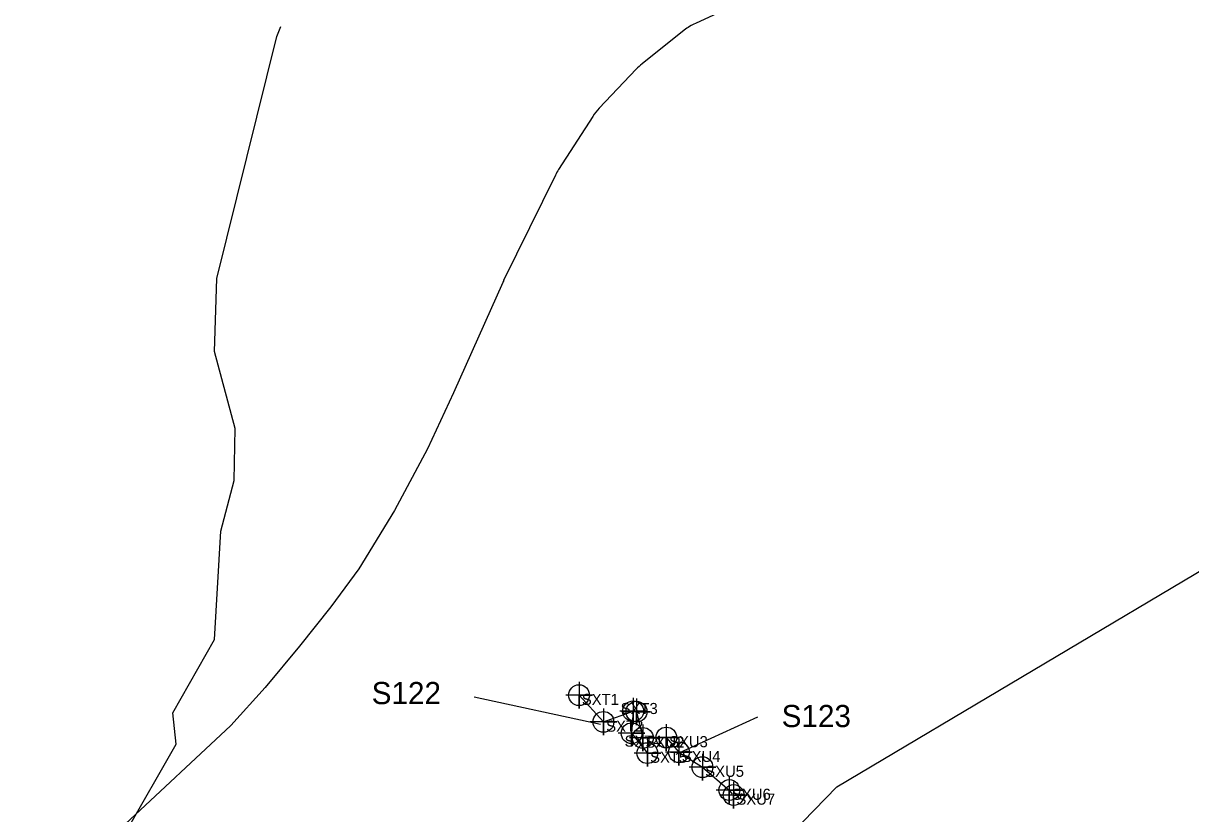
# Model space of a CAD drawing. Extents: x 1253697 to 1278588, y 912189 to 981699.
# Drawn here: x 1265224 to 1266277, y 963801 to 964514 of the extents above; entities that cross this region are included whole.
import ezdxf

# ---------------------------------------------------------------- set-up
doc = ezdxf.new("R2010")
doc.units = 0
for name, color, linetype in [('Default', 7, 'Continuous'), ('Exist Hydro Jurisdictional Stream or Body of Water Mitigable', 7, 'Continuous'), ('Exist Hydro Jurisdictional Stream or Body of Water Mitigable Cogo Comment', 7, 'Continuous'), ('Exist Hydro Jurisdictional Stream or Body of Water Mitigable Cogo Number', 7, 'Continuous'), ('Exist Hydro Jurisdictional Stream or Body of Water Mitigable Cogo Point CELL', 7, 'Continuous')]:
    doc.layers.add(name, color=color, linetype=linetype)

msp = doc.modelspace()

# ---------------------------------------------------------------- linework, layer by layer
at = {"layer": 'Default'}
for p, q in [((1265819.9, 964507.3), (1265781.8, 964477)), ((1265819.9, 964507.3), (1265781.8, 964477)), ((1265776.6, 964472.3), (1265743.1, 964437)), ((1265776.6, 964472.3), (1265743.1, 964437)), ((1265737.3, 964429.6), (1265706.6, 964381.8)), ((1265737.3, 964429.6), (1265706.6, 964381.8)), ((1265703.8, 964376.8), (1265657, 964281.8)), ((1265703.8, 964376.8), (1265657, 964281.8)), ((1265630.3, 963906.7), (1265744.4, 963882)), ((1265812.5, 963854.8), (1265886.1, 963888.7))]:
    msp.add_line(p, q, dxfattribs=at)
for points in [[(1266254.7, 964871.1), (1266198.6, 964805.2), (1266142.8, 964740.7), (1266058.3, 964648.7), (1265988.3, 964590.9), (1265917.3, 964554.1), (1265829.9, 964513.5)], [(1266254.7, 964871.1), (1266198.6, 964805.2), (1266142.8, 964740.7), (1266058.3, 964648.7), (1265988.3, 964590.9), (1265917.3, 964554.1), (1265829.9, 964513.5)], [(1265656.2, 964280.1), (1265611.8, 964180.6), (1265588.2, 964130), (1265558.7, 964074.4), (1265526.4, 964022), (1265501.2, 963987.7), (1265473, 963952.4), (1265441.9, 963915), (1265411.1, 963880.7), (1265315.8, 963792)], [(1265656.2, 964280.1), (1265611.8, 964180.6), (1265588.2, 964130), (1265558.7, 964074.4), (1265526.4, 964022), (1265501.2, 963987.7), (1265473, 963952.4), (1265441.9, 963915), (1265411.1, 963880.7), (1265315.8, 963792)], [(1265661.4, 963520.8), (1265957.6, 963825.6), (1266311.4, 964035.8), (1266558.5, 964182.7)], [(1265661.4, 963520.8), (1265957.6, 963825.6), (1266311.4, 964035.8), (1266558.5, 964182.7)]]:
    msp.add_lwpolyline(points, dxfattribs=at)
for centre, start, end in [((1265851, 964468.2), 114.9211, 128.488), ((1265851, 964468.2), 114.9211, 128.488), ((1265812.9, 964437.9), 128.488, 136.5087), ((1265812.9, 964437.9), 128.488, 136.5087), ((1265779.4, 964402.6), 136.5087, 147.2537), ((1265779.4, 964402.6), 136.5087, 147.2537), ((1265748.6, 964354.7), 147.2537, 153.8126), ((1265748.6, 964354.7), 147.2537, 153.8126), ((1265701.9, 964259.7), 153.8126, 155.9113), ((1265701.9, 964259.7), 153.8126, 155.9113)]:
    msp.add_arc(centre, 50, start, end, dxfattribs=at)
at = {"layer": 'Exist Hydro Jurisdictional Stream or Body of Water Mitigable'}
for points in [[(1265223.9, 963646.4), (1265277.6, 963743.4), (1265316.3, 963784.6), (1265361.7, 963864.1), (1265358.7, 963892.2), (1265396.3, 963958.3), (1265402, 964055.9), (1265414.1, 964101.5), (1265414.9, 964148.5), (1265396.2, 964217.7), (1265398.3, 964283.5), (1265452.4, 964501.7), (1265456.1, 964510.6)], [(1265725, 963908.1), (1265747, 963884), (1265773.8, 963893.6), (1265772.4, 963873.8), (1265786.6, 963855.9)], [(1265776.8, 963893.2), (1265782.5, 963869.6), (1265803.7, 963869.9), (1265815.1, 963856.7), (1265836.3, 963843.2), (1265860.5, 963822.6), (1265863, 963818.8)]]:
    msp.add_lwpolyline(points, dxfattribs=at)
at = {"layer": 'Exist Hydro Jurisdictional Stream or Body of Water Mitigable Cogo Point CELL'}
for points in [[(1265725, 963920.1), (1265725, 963896.1), (1265725, 963908.1), (1265737, 963908.1), (1265713, 963908.1)], [(1265773.8, 963905.6), (1265773.8, 963881.6), (1265773.8, 963893.6), (1265785.8, 963893.6), (1265761.8, 963893.6)], [(1265776.8, 963905.2), (1265776.8, 963881.2), (1265776.8, 963893.2), (1265788.8, 963893.2), (1265764.8, 963893.2)], [(1265747, 963896), (1265747, 963872), (1265747, 963884), (1265759, 963884), (1265735, 963884)], [(1265772.4, 963885.8), (1265772.4, 963861.8), (1265772.4, 963873.8), (1265784.4, 963873.8), (1265760.4, 963873.8)], [(1265782.5, 963881.6), (1265782.5, 963857.6), (1265782.5, 963869.6), (1265794.5, 963869.6), (1265770.5, 963869.6)], [(1265803.7, 963881.9), (1265803.7, 963857.9), (1265803.7, 963869.9), (1265815.7, 963869.9), (1265791.7, 963869.9)], [(1265786.6, 963867.9), (1265786.6, 963843.9), (1265786.6, 963855.9), (1265798.6, 963855.9), (1265774.6, 963855.9)], [(1265815.1, 963868.7), (1265815.1, 963844.7), (1265815.1, 963856.7), (1265827.1, 963856.7), (1265803.1, 963856.7)], [(1265836.3, 963855.2), (1265836.3, 963831.2), (1265836.3, 963843.2), (1265848.3, 963843.2), (1265824.3, 963843.2)], [(1265860.5, 963834.6), (1265860.5, 963810.6), (1265860.5, 963822.6), (1265872.5, 963822.6), (1265848.5, 963822.6)], [(1265864.4, 963830.1), (1265864.4, 963806.1), (1265864.4, 963818.1), (1265876.4, 963818.1), (1265852.4, 963818.1)]]:
    msp.add_lwpolyline(points, dxfattribs=at)
for centre in [(1265725, 963908.1), (1265773.8, 963893.6), (1265776.8, 963893.2), (1265747, 963884), (1265772.4, 963873.8), (1265782.5, 963869.6), (1265803.7, 963869.9), (1265786.6, 963855.9), (1265815.1, 963856.7), (1265836.3, 963843.2), (1265860.5, 963822.6), (1265864.4, 963818.1)]:
    msp.add_circle(centre, 9.38, dxfattribs=at)

# ---------------------------------------------------------------- texts
at = {"layer": 'Exist Hydro Jurisdictional Stream or Body of Water Mitigable Cogo Comment'}
for s, p in [('SXT1', (1265727.5, 963899.3)), ('SXT3', (1265762.5, 963891.1)), ('SXT2', (1265749.5, 963875.2)), ('SXT4', (1265766.1, 963861.7)), ('SXU2', (1265785, 963860.8)), ('SXU3', (1265806.2, 963861.2)), ('SXT5', (1265789.1, 963847.2)), ('SXU4', (1265817.6, 963847.9)), ('SXU5', (1265838.8, 963834.5)), ('SXU6', (1265863, 963813.8)), ('SXU7', (1265866.9, 963809.4))]:
    msp.add_text(s, height=10, dxfattribs=at).set_placement(p)
at = {"layer": 'Exist Hydro Jurisdictional Stream or Body of Water Mitigable Cogo Number'}
for s, p in [('S122', (1265538, 963900)), ('S123', (1265907.7, 963879.3))]:
    msp.add_text(s, height=20, dxfattribs=at).set_placement(p)

doc.saveas('drawing.dxf')
